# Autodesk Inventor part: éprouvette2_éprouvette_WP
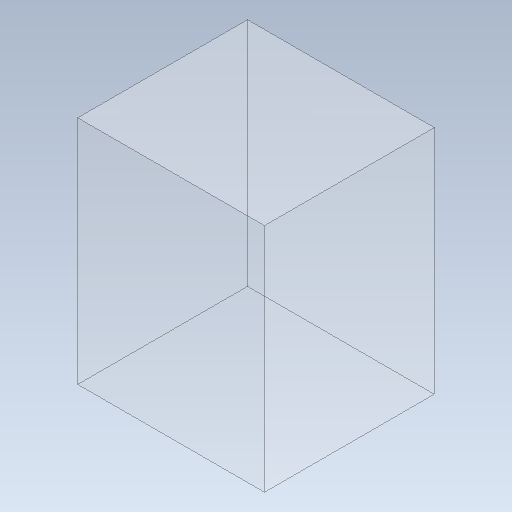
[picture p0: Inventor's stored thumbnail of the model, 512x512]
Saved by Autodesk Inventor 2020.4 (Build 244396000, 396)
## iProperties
Created: 2021-10
Part Number: éprouvette2_éprouvette_WP
Material: Générique
Document SubType Name: Modeling
Designer: mel
Density: 1 g/cm^3
Appearance: Par défaut
Author: mel
d0: -25,000 mm
d1: 27,500 mm
d2: 27,500 mm
d3: 34,000 mm
d4: 34,000 mm
d5: 50,000 mm
d6: 0,00 deg
Xmin: -27,500 mm
Ymin: -34,000 mm
Zmin: -25,000 mm
Xmax: 27,500 mm
Ymax: 34,000 mm
Zmax: 25,000 mm
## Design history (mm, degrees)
sketch "Esquisse1"
  geometry: L1 (-27.5, 34)-(27.5, 34); L2 (27.5, 34)-(27.5, -34); L3 (27.5, -34)-(-27.5, -34); L4 (-27.5, -34)-(-27.5, 34); 1 further point
  constraints: 8 end point, 2 parallel, 1 horizontal, 1 perpendicular, 1 other
  dimensions: "d1" = 27.5 distance from line of L4 point (0, 0) (= -Xmin); "d2" = 27.5 distance from line of L2 point (0, 0) (= Xmax); "d3" = 34 distance from line of L3 point (0, 0) (= -Ymin); "d4" = 34 distance from line of L1 point (0, 0) (= Ymax)
extrude "Extrusion1" join sketch "Esquisse1" distance "d5" = 50 (= Zmax - Zmin); taper "d6" = 0 deg
node "Solide1"
other parameters: "Xmin" = -27.5 [user parameter; used in 1 equation term], "Ymin" = -34 [user parameter; used in 1 equation term], "Zmin" = -25 [user parameter; used in 1 equation term], "Xmax" = 27.5 [user parameter; used in 1 equation term], "Ymax" = 34 [user parameter; used in 1 equation term], "Zmax" = 25 [user parameter; used in 1 equation term], "d0" = -25
